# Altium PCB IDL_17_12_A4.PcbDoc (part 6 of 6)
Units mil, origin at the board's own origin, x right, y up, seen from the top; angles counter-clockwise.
Board outline 3172.06 x 10350 mil, 6 copper layers (Top Signal, Mid Signal, 3.3 Volt, GND, 5 Volt, Bot Signal), stack 122.8 mil thick; 332 components, 120 nets, 1937 pads, 197 vias.
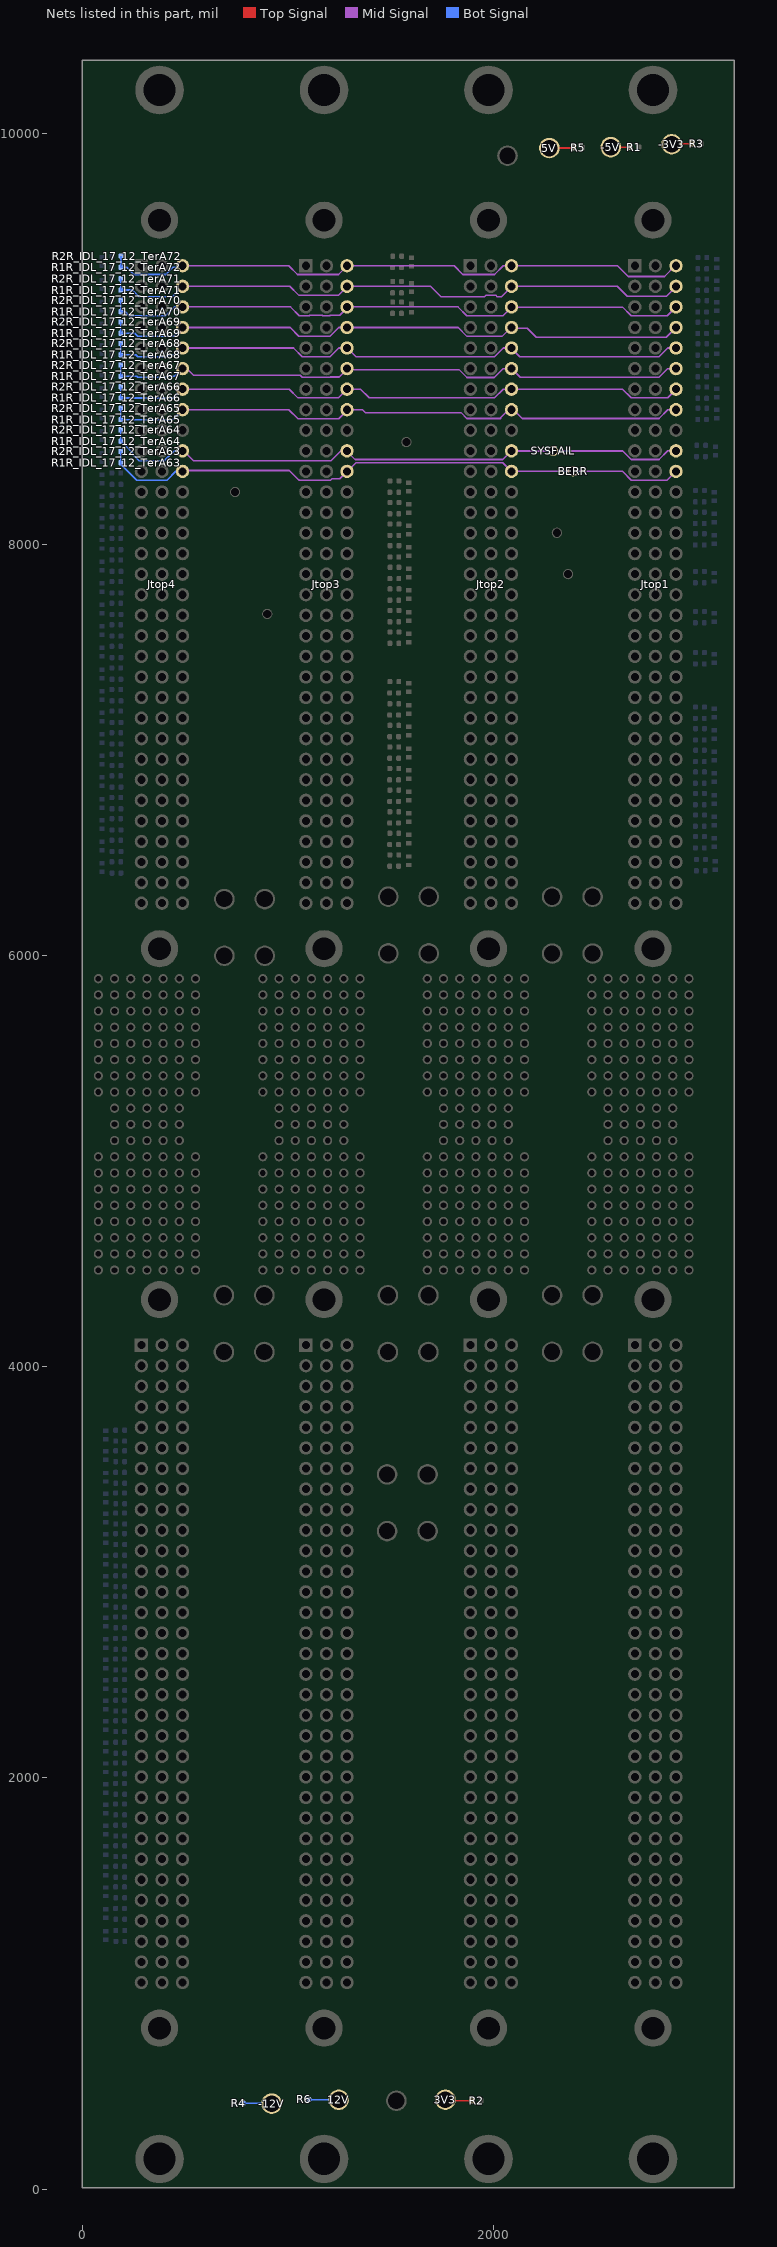
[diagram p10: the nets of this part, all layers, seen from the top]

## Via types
v1: diameter 25.59, hole 12, Top Signal to Bot Signal, 197 vias

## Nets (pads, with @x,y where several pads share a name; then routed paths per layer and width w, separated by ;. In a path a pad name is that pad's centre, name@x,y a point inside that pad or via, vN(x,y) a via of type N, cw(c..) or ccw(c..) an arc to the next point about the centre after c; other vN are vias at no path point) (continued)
JT63: BERR.1 Jtop1.C11 Jtop2.C11 Jtop3.C11 Jtop4.C11 R1R_IDL_17_12_TerA63.1 R2R_IDL_17_12_TerA63.2 | length 2955.1
  Mid Signal w8: Jtop4.C11@488.16,8354.97 488.16,8359.11 1007.69,8359.11 1052.43,8314.37 1052.76,8314.7 1056.02,8311.45 1207.56,8311.45 1215.18,8319.06 1253.26,8319.06 Jtop3.C11@1288.53,8354.33 ; Jtop3.C11@1288.61,8354.56 1331.5,8397.45 2045.68,8397.45 Jtop2.C11@2088.16,8354.97 2387.48,8354.97 2628.08,8354.97 2670.57,8312.48 2844.25,8312.48 2887.44,8355.68 2887.93,8356.16 Jtop1.C11@2888.16,8354.97
  Bot Signal w8: R2R_IDL_17_12_TerA63.2@187.5,8451.99 187.5,8424.61 ; R1R_IDL_17_12_TerA63.1@188.37,8396.97 188.37,8423.73 187.5,8424.61 ; Jtop4.C11@488.16,8354.97 455.51,8354.97 412.28,8311.73 265.28,8311.73 187.5,8389.52 187.5,8396.97 187.5,8424.61
JT64: Jtop1.C10 Jtop2.C10 Jtop3.C10 Jtop4.C10 R1R_IDL_17_12_TerA64.1 R2R_IDL_17_12_TerA64.2 SYSFAIL.1 | length 2942.3
  Mid Signal w8: Jtop4.C10@488.16,8454.97 488.9,8458.48 490.29,8457.09 541.31,8406.07 1210,8406.07 1258.89,8454.97 Jtop3.C10@1284.9,8454.97 ; Jtop3.C10@1283.19,8456.67 Jtop3.C10@1284.9,8454.97 ; Jtop3.C10@1288.16,8454.97 Jtop3.C10@1284.9,8454.97 ; Jtop2.C10@2084.72,8453.96 Jtop2.C10@2087.16,8453.96 ; Jtop2.C10@2088.16,8454.97 Jtop2.C10@2087.16,8453.96 ; Jtop1.C10@2888.16,8454.97 2848.24,8454.97 2805.76,8412.49 2670.57,8412.49 2629.09,8453.96 2290.4,8453.96 2088.16,8453.96 Jtop2.C10@2087.16,8453.96 ; Jtop3.C10@1284.9,8454.97 1286.53,8453.34 1327.38,8412.49 2045.68,8412.49 Jtop2.C10@2087.16,8453.96
  Bot Signal w8: R2R_IDL_17_12_TerA64.2@187.5,8556.99 187.5,8505.93 R1R_IDL_17_12_TerA64.1@189.68,8503.74 ; R1R_IDL_17_12_TerA64.1@188.37,8501.97 245.68,8444.66 245.68,8437.37 276.7,8406.36 399.63,8406.36 447.31,8454.04 488.16,8454.04 Jtop4.C10@488.95,8454.04
JT65: Jtop1.C8 Jtop2.C8 Jtop3.C8 Jtop4.C8 R1R_IDL_17_12_TerA65.1 R2R_IDL_17_12_TerA65.2 | length 2941.2
  Mid Signal w8: Jtop4.C8@488.16,8654.97 1005.35,8654.97 1049.34,8610.98 1247.85,8610.98 1287.24,8650.36 Jtop3.C8@1288.16,8654.97 ; Jtop3.C8@1293.11,8654.33 Jtop3.C8@1288.16,8654.97 ; 2031.79,8612.84 2073.92,8654.97 Jtop2.C8@2088.16,8654.97 2088.16,8675.73 2102.28,8675.73 2102.28,8654.97 2102.28,8654.38 2098.34,8654.38 2140.24,8612.48 2805.76,8612.48 2848.24,8654.97 Jtop1.C8@2888.16,8654.97 ; 2034.68,8612.49 1870.57,8612.49 1842.09,8640.97 1377.46,8640.97 1363.46,8654.97 Jtop3.C8@1288.16,8654.97
  Bot Signal w8: R2R_IDL_17_12_TerA65.2@187.5,8661.99 187.5,8634.61 188.37,8633.73 R1R_IDL_17_12_TerA65.1@188.37,8606.97 440.16,8606.97 Jtop4.C8@488.16,8654.97
JT66: Jtop1.C7 Jtop2.C7 Jtop3.C7 Jtop4.C7 R1R_IDL_17_12_TerA66.1 R2R_IDL_17_12_TerA66.2 | length 2886.7
  Mid Signal w8: Jtop4.C7@488.16,8754.96 1006.98,8754.96 1049.66,8712.28 1246.09,8712.28 1285.91,8752.1 Jtop3.C7@1288.16,8754.96 1289.57,8754.96 1289.57,8751.92 1290.38,8752.74 1292.61,8754.96 1353.33,8754.96 1395.8,8712.49 2005.76,8712.49 2048.24,8754.96 Jtop2.C7@2088.16,8754.96 2628.09,8754.96 2670.57,8712.49 2848.12,8712.49 2889.38,8753.75 2889.6,8753.97 Jtop1.C7@2888.16,8754.97
  Bot Signal w8: R2R_IDL_17_12_TerA66.2@187.5,8766.99 187.5,8715.42 189.66,8713.25 R1R_IDL_17_12_TerA66.1@190.95,8711.97 ; R1R_IDL_17_12_TerA66.1@188.37,8711.97 R1R_IDL_17_12_TerA66.1@190.95,8711.97 ; Jtop4.C7@488.16,8754.96 483.37,8753.81 441.53,8711.97 R1R_IDL_17_12_TerA66.1@190.95,8711.97
JT67: Jtop1.C6 Jtop2.C6 Jtop3.C6 Jtop4.C6 R1R_IDL_17_12_TerA67.1 R2R_IDL_17_12_TerA67.2 | length 2886
  Mid Signal w8: Jtop4.C6@488.16,8854.97 508.81,8854.97 541.83,8821.95 1061.1,8821.95 1070.57,8812.49 1105.76,8812.49 1106.38,8813.1 1169.01,8813.1 1169.63,8812.49 1205.76,8812.49 1207.31,8814.04 1250.52,8814.04 1289.8,8853.32 1290.34,8853.85 Jtop3.C6@1288.16,8854.97 ; Jtop3.C6@1289.09,8850.06 1832.99,8850.06 1871.6,8811.45 2004.72,8811.45 2048.24,8854.97 Jtop2.C6@2088.16,8854.97 ; Jtop2.C6@2089.74,8853.81 2131.06,8812.49 2805.76,8812.49 2848.24,8854.97 Jtop1.C6@2888.16,8854.97
  Bot Signal w8: R2R_IDL_17_12_TerA67.2@187.5,8871.99 187.5,8821.43 R1R_IDL_17_12_TerA67.1@190.17,8818.76 ; R1R_IDL_17_12_TerA67.1@188.37,8816.97 266.09,8816.97 270.57,8812.49 405.76,8812.49 410.24,8816.97 449.65,8816.97 487.9,8855.22 Jtop4.C6@492.5,8859.82
JT68: Jtop1.C5 Jtop2.C5 Jtop3.C5 Jtop4.C5 R1R_IDL_17_12_TerA68.1 R2R_IDL_17_12_TerA68.2 | length 2900.6
  Mid Signal w8: Jtop4.C5@488.16,8954.97 1028.09,8954.97 1070.57,8912.49 1205.76,8912.49 1248.24,8954.97 1286.84,8954.97 Jtop3.C5@1287.33,8954.48 ; Jtop3.C5@1288.16,8954.96 1286.35,8958.42 1288.98,8955.79 1332.29,8912.49 2005.76,8912.49 2048.24,8954.97 Jtop2.C5@2085.3,8954.97 ; Jtop2.C5@2083.81,8956.45 Jtop2.C5@2085.3,8954.97 ; Jtop2.C5@2088.16,8954.97 Jtop2.C5@2085.3,8954.97 ; Jtop1.C5@2888.16,8954.97 2848.24,8954.97 2805.76,8912.49 2127.78,8912.49 2086.73,8953.54 Jtop2.C5@2085.3,8954.97
  Bot Signal w8: R1R_IDL_17_12_TerA68.1@185.63,8917.14 187.5,8919.01 187.5,8921.97 R2R_IDL_17_12_TerA68.2@187.5,8976.99 ; R1R_IDL_17_12_TerA68.1@188.37,8921.97 261.08,8921.97 270.57,8912.48 405.76,8912.48 415.24,8921.97 459.29,8921.97 490.22,8952.9 Jtop4.C5@490.47,8953.15
JT69: Jtop1.C4 Jtop2.C4 Jtop3.C4 Jtop4.C4 R1R_IDL_17_12_TerA69.1 R2R_IDL_17_12_TerA69.2 | length 2890
  Mid Signal w8: Jtop4.C4@488.16,9054.97 1011.36,9054.97 1053.84,9012.49 1205.76,9012.49 1248.24,9054.97 Jtop3.C4@1288.16,9054.97 1288.6,9054.97 1290.05,9053.51 1291.71,9054.62 1828.43,9054.62 1871.6,9011.45 2042,9011.45 2086.84,9056.29 Jtop2.C4@2088.6,9058.04 ; Jtop2.C4@2090.82,9050.99 2164.85,9050.99 2208.4,9007.44 2840.64,9007.44 Jtop1.C4@2888.16,9054.97
  Bot Signal w8: R1R_IDL_17_12_TerA69.1@186.64,9023.66 187.5,9024.51 187.5,9026.97 R2R_IDL_17_12_TerA69.2@187.5,9081.99 ; R1R_IDL_17_12_TerA69.1@188.37,9026.97 256.09,9026.97 270.57,9012.49 445.32,9012.49 Jtop4.C4@487.43,9054.6
JT70: Jtop1.C3 Jtop2.C3 Jtop3.C3 Jtop4.C3 R1R_IDL_17_12_TerA70.1 R2R_IDL_17_12_TerA70.2 | length 2898.1
  Mid Signal w8: Jtop4.C3@488.16,9154.96 1012.93,9154.96 1055.41,9112.48 1105.76,9112.48 1107.19,9113.92 1169.13,9113.92 1170.57,9112.48 1205.76,9112.48 1207.19,9113.92 1253.26,9113.92 1290.28,9150.94 Jtop3.C3@1288.16,9154.97 1828.08,9154.97 1870.57,9112.48 2047.21,9112.48 2088.8,9154.08 2628.02,9154.08 2668.45,9113.65 ; 2668.93,9114.12 2670.57,9112.48 2846.44,9112.48 2888.54,9154.58 Jtop1.C3@2890.26,9156.3
  Bot Signal w8: R2R_IDL_17_12_TerA70.2@187.5,9186.99 187.5,9134.55 189.22,9132.82 R1R_IDL_17_12_TerA70.1@190.08,9131.97 ; R1R_IDL_17_12_TerA70.1@188.37,9131.97 191.05,9130.99 R1R_IDL_17_12_TerA70.1@190.08,9131.97 ; Jtop4.C3@488.16,9154.96 448.24,9154.96 405.01,9111.73 229.28,9111.73 209.05,9131.97 R1R_IDL_17_12_TerA70.1@190.08,9131.97
JT71: Jtop1.C2 Jtop2.C2 Jtop3.C2 Jtop4.C2 R1R_IDL_17_12_TerA71.1 R2R_IDL_17_12_TerA71.2 | length 2926
  Mid Signal w8: Jtop4.C2@488.16,9254.97 1010.14,9254.97 1052.62,9212.48 1247.93,9212.48 1289.28,9253.84 Jtop3.C2@1290.41,9254.97 ; Jtop3.C2@1288.16,9254.97 Jtop3.C2@1290.41,9254.97 ; Jtop1.C2@2888.16,9254.97 2892.49,9256.69 2889.47,9253.66 2842.3,9206.49 2651.57,9206.49 2603.1,9254.97 Jtop2.C2@2088.16,9254.97 2088.16,9250.01 2085.71,9250.01 2040.84,9205.14 2017.86,9205.14 2011.56,9211.45 1964.77,9211.45 1958.46,9205.14 1743.75,9205.14 1693.92,9254.97 Jtop3.C2@1290.41,9254.97
  Bot Signal w8: R2R_IDL_17_12_TerA71.2@187.5,9291.99 187.5,9264.61 188.37,9263.73 R1R_IDL_17_12_TerA71.1@188.37,9236.97 244.05,9236.97 276.28,9204.73 437.93,9204.73 Jtop4.C2@488.16,9254.97
JT72: Jtop1.C1 Jtop2.C1 Jtop3.C1 Jtop4.C1 R1R_IDL_17_12_TerA72.1 R2R_IDL_17_12_TerA72.2 | length 2901.5
  Mid Signal w8: Jtop4.C1@488.16,9354.97 1004.72,9354.97 1047.2,9312.49 1246.89,9312.49 Jtop3.C1@1287.43,9353.03 ; Jtop3.C1@1288.16,9354.97 1809.06,9354.97 1851.54,9312.49 2005.76,9312.49 2048.24,9354.97 Jtop2.C1@2088.16,9354.97 2603.6,9354.97 2655.51,9303.06 2832.17,9303.06 2886.12,9357.01 Jtop1.C1@2886.66,9357.56
  Bot Signal w8: R1R_IDL_17_12_TerA72.1@188.36,9347.52 216.51,9347.52 251.54,9312.49 405.76,9312.49 440.79,9347.52 484.13,9347.52 489.87,9353.26 490.47,9353.86 Jtop4.C1@488.16,9354.97 ; R2R_IDL_17_12_TerA72.2@188.62,9402.03 188.62,9348.33 R1R_IDL_17_12_TerA72.1@188.67,9348.28
TP3V3_2: 3V3.1@1766.37,434.93 R2.1 | length 129.2
  Top Signal w8: 3V3.1@1769.47,435.28 1774.83,429.92 R2.1@1896.47,429.92
TP5V_2: 5V.1@2272.26,9927.69 R5.1 | length 126.3
  Top Signal w8: 5V.1@2265.37,9928.08 2272.26,9928.08 2390.15,9928.08 R5.1@2391.2,9929.14
TP12V_2: 12V.1@1247.83,434.61 R6.1 | length 144.6
  Bot Signal w8: R6.1@1101.56,435.56 1102.44,435.56 1244.33,435.56 12V.1@1245.61,436.84
TP-3V3_2: -3V3.1@2867.29,9946.36 R3.1 | length 77.9
  Top Signal w8: -3V3.1@2890.7,9951.9 2893.87,9948.74 R3.1@2967.27,9948.74
TP-5V_2: -5V.1@2571.02,9932.41 R1.1 | length 83
  Top Signal w8: -5V.1@2582.33,9930.01 2584.05,9931.73 R1.1@2664.58,9931.73
TP-12V_2: -12V.1@921.62,416.17 R4.1 | length 136.6
  Bot Signal w8: R4.1@782.89,417.54 912.71,417.54 916.48,421.31 -12V.1@917.5,422.32
pads on no net: Jbot1.33 Jbot1.34 Jbot1.A1 Jbot1.A2 Jbot1.A3 Jbot1.A4 Jbot1.A5 Jbot1.A6 Jbot1.A7 Jbot1.A8 Jbot1.A9 Jbot1.A10 Jbot1.A11 Jbot1.A12 Jbot1.A13 Jbot1.A14 Jbot1.A15 Jbot1.A16 Jbot1.A17 Jbot1.A18 Jbot1.A19 Jbot1.A20 Jbot1.A21 Jbot1.A22 Jbot1.A23 Jbot1.A24 Jbot1.A25 Jbot1.A26 Jbot1.A27 Jbot1.A28 Jbot1.A29 Jbot1.A30 Jbot1.A31 Jbot1.A32 Jbot1.C1 Jbot1.C2 Jbot1.C3 Jbot1.C4 Jbot1.C5 Jbot1.C6 Jbot1.C7 Jbot1.C8 Jbot1.C9 Jbot1.C10 Jbot1.C11 Jbot1.C12 Jbot1.C13 Jbot1.C14 Jbot1.C15 Jbot1.C16 Jbot1.C17 Jbot1.C18 Jbot1.C19 Jbot1.C20 Jbot1.C21 Jbot1.C22 Jbot1.C23 Jbot1.C24 Jbot1.C25 Jbot1.C26 Jbot1.C27 Jbot1.C28 Jbot1.C29 Jbot1.C30 Jbot1.C31 Jbot1.C32 Jbot2.33 Jbot2.34 Jbot2.A1 Jbot2.A2 Jbot2.A3 Jbot2.A4 Jbot2.A5 Jbot2.A6 Jbot2.A7 Jbot2.A8 Jbot2.A9 Jbot2.A10 Jbot2.A11 Jbot2.A12 Jbot2.A13 Jbot2.A14 Jbot2.A15 Jbot2.A16 Jbot2.A17 Jbot2.A18 Jbot2.A19 Jbot2.A20 Jbot2.A21 Jbot2.A22 Jbot2.A23 Jbot2.A24 Jbot2.A25 Jbot2.A26 Jbot2.A27 Jbot2.A28 Jbot2.A29 Jbot2.A30 Jbot2.A31 Jbot2.A32 Jbot2.C1 Jbot2.C2 Jbot2.C3 Jbot2.C4 Jbot2.C5 Jbot2.C6 Jbot2.C7 Jbot2.C8 Jbot2.C9 Jbot2.C10 Jbot2.C11 Jbot2.C12 Jbot2.C13 Jbot2.C14 Jbot2.C15 Jbot2.C16 Jbot2.C17 Jbot2.C18 Jbot2.C19 Jbot2.C20 Jbot2.C21 Jbot2.C22 Jbot2.C23 Jbot2.C24 Jbot2.C25 Jbot2.C26 Jbot2.C27 Jbot2.C28 Jbot2.C29 Jbot2.C30 Jbot2.C31 Jbot2.C32 Jbot3.33 Jbot3.34 Jbot3.A1 Jbot3.A2 Jbot3.A3 Jbot3.A4 Jbot3.A5 Jbot3.A6 Jbot3.A7 Jbot3.A8 Jbot3.A9 Jbot3.A10 Jbot3.A11 Jbot3.A12 Jbot3.A13 Jbot3.A14 Jbot3.A15 Jbot3.A16 Jbot3.A17 Jbot3.A18 Jbot3.A19 Jbot3.A20 Jbot3.A21 Jbot3.A22 Jbot3.A23 Jbot3.A24 Jbot3.A25 Jbot3.A26 Jbot3.A27 Jbot3.A28 Jbot3.A29 Jbot3.A30 Jbot3.A31 Jbot3.A32 Jbot3.C1 Jbot3.C2 Jbot3.C3 Jbot3.C4 Jbot3.C5 Jbot3.C6 Jbot3.C7 Jbot3.C8 Jbot3.C9 Jbot3.C10 Jbot3.C11 Jbot3.C12 Jbot3.C13 Jbot3.C14 Jbot3.C15 Jbot3.C16 Jbot3.C17 Jbot3.C18 Jbot3.C19 Jbot3.C20 Jbot3.C21 Jbot3.C22 Jbot3.C23 Jbot3.C24 Jbot3.C25 Jbot3.C26 Jbot3.C27 Jbot3.C28 Jbot3.C29 Jbot3.C30 Jbot3.C31 Jbot3.C32 Jbot4.33 Jbot4.34 Jbot4.A1 Jbot4.A2 Jbot4.A3 Jbot4.A4 Jbot4.A5 Jbot4.A6 Jbot4.A7 Jbot4.A8 Jbot4.A9 Jbot4.A10 Jbot4.A11 Jbot4.A12 Jbot4.A13 Jbot4.A14 Jbot4.A15 Jbot4.A16 Jbot4.A17 Jbot4.A18 Jbot4.A19 Jbot4.A20 Jbot4.A21 Jbot4.A22 Jbot4.A23 Jbot4.A24 Jbot4.A25 Jbot4.A26 Jbot4.A27 Jbot4.A28 Jbot4.A29 Jbot4.A30 Jbot4.A31 Jbot4.A32 Jbot4.C1 Jbot4.C2 Jbot4.C3 Jbot4.C4 Jbot4.C5 Jbot4.C6 Jbot4.C7 Jbot4.C8 Jbot4.C9 Jbot4.C10 Jbot4.C11 Jbot4.C12 Jbot4.C13 Jbot4.C14 Jbot4.C15 Jbot4.C16 Jbot4.C17 Jbot4.C18 Jbot4.C19 Jbot4.C20 Jbot4.C21 Jbot4.C22 Jbot4.C23 Jbot4.C24 Jbot4.C25 Jbot4.C26 Jbot4.C27 Jbot4.C28 Jbot4.C29 Jbot4.C30 Jbot4.C31 Jbot4.C32 JMid1.32 JMid1.33 JMid1.34 JMid1.35 JMid1.51 JMid1.52 JMid1.53 JMid1.54 JMid1.89 JMid1.90 JMid1.91 JMid1.92 JMid1.102 JMid1.103 JMid1.104 JMid1.106 JMid1.108 JMid1.109 JMid1.110 JMid1.111 JMid2.32 JMid2.33 JMid2.34 JMid2.35 JMid2.51 JMid2.52 JMid2.53 JMid2.54 JMid2.89 JMid2.90 JMid2.91 JMid2.92 JMid2.102 JMid2.103 JMid2.104 JMid2.106 JMid2.108 JMid2.109 JMid2.110 JMid2.111 JMid3.32 JMid3.33 JMid3.34 JMid3.35 JMid3.51 JMid3.52 JMid3.53 JMid3.54 JMid3.89 JMid3.90 JMid3.91 JMid3.92 JMid3.102 JMid3.103 JMid3.104 JMid3.106 JMid3.108 JMid3.109 JMid3.110 JMid3.111 JMid4.32 JMid4.33 JMid4.34 JMid4.35 JMid4.51 JMid4.52 JMid4.53 JMid4.54 JMid4.89 JMid4.90 JMid4.91 JMid4.92 JMid4.102 JMid4.103 JMid4.104 JMid4.106 JMid4.108 JMid4.109 JMid4.110 JMid4.111 Jtop1.33 Jtop1.34 Jtop2.33 Jtop2.34 Jtop3.33 Jtop3.34 Jtop4.33 Jtop4.34

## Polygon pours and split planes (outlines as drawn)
GND on Mid Signal "Mid Signal-No Net" (solid, remove dead copper, pour order 8): 288.97,2902.97 292.43,2899.5 2892.14,2899.5 2892.14,881.35 2781.37,770.58 2774.45,777.5 295.89,777.5 295.89,2909.89
12V on Mid Signal "12V" (solid, remove dead copper, pour order 4): 102.79,6460.34 110.33,6467.88 3031.85,6467.88 3031.85,5887.72 3028.09,5883.95 102.79,5883.95
-5V on Mid Signal "-5V" (solid, remove dead copper, pour order 0): 80.39,4937.59 82.87,4940.06 2954.79,4940.06 2949.84,3073.97 76.86,3073.97 82.87,3303.91 77.92,3563.42 77.92,3633.46
-3V3 on Top Signal "-3V3" (solid, remove dead copper, pour order 2): 72.6,5264.94 2949.49,5264.94 2949.49,3892.71 66.5,3892.71 56.18,3892.71
-12V on Top Signal "-12V" (solid, remove dead copper, pour order 6): 226.59,6445.99 2946.13,6445.99 2946.13,5895.87 226.59,5895.87
-12V on Top Solder "-12V" (solid, remove dead copper): 104.53,6466.91 3032.29,6466.91 3034.17,6465.03 3024.77,6455.63 3024.77,5891.52 102.65,5891.52
3V3 on 3.3 Volt (split plane): 3151.24,25.83 20.37,25.83 20.37,10335.64 3151.24,10335.64
GND on GND (split plane): 3151.24,25.83 19.38,25.83 19.38,10335.64 3151.24,10335.64
5V on 5 Volt (split plane): 3151.24,25.83 20.37,25.83 20.37,10335.64 3151.24,10335.64

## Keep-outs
Keep-Out Layer:
  lines w20: -0.72,5.73 -0.72,10355.73

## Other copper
3.3 Volt (plane layer: these items are gaps in the copper):
  lines w20: 10.28,16.73 10.28,10344.73
5 Volt (plane layer: these items are gaps in the copper):
  lines w20: 10.28,16.73 10.28,10344.73

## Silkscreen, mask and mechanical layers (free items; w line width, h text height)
Top Overlay:
  lines w10: 58.79,5133.09 101.87,5133.09 101.87,5219.98 58.79,5219.98 58.79,5133.09 ; 856.31,5137.1 856.31,5223.99 899.39,5223.99 899.39,5137.1 856.31,5137.1 ; 1655.2,5137.36 1655.2,5224.24 1698.28,5224.24 1698.28,5137.36 1655.2,5137.36 ; 2442.3,5138.09 2442.3,5224.97 2485.38,5224.97 2485.38,5138.09 2442.3,5138.09
  lines w15.66: 524.81,5107.15 524.81,5243.24 592.29,5243.24 592.29,5107.15 524.81,5107.15 ; 1327.71,5110.36 1395.19,5110.36 1395.19,5246.44 1327.71,5246.44 1327.71,5110.36 ; 2120.23,5112.58 2187.71,5112.58 2187.71,5248.66 2120.23,5248.66 2120.23,5112.58 ; 2922.08,5112.43 2989.56,5112.43 2989.56,5248.51 2922.08,5248.51 2922.08,5112.43
  text "1" at 2477.89,9369.12 h60 r270
Bottom Overlay:
  drawing of 175 lines, arcs and shapes, not listed
  text "Jtop1" at 3095.97,9777.19 h60 r90
  text "IDL_17_012 / VME32/COPPER Backplane Rev.A / Designer: Jose Duron" at 1393.36,9710.53 h60
  text "A" at 1867.39,9406.06 h60 r270
  text "A" at 268.09,9402.68 h60 r270
  text "A" at 1070.53,9402.97 h60 r270
  text "A" at 2669.1,9400.38 h60 r270
  text "1" at 2476.52,9369.05 h60 r270
  text "1" at 573.67,9345.91 h60 r270
  text "1" at 1687.9,9339.53 h60 r270
  text "1" at 884.85,9333.34 h60 r270
  text "Jtop2" at 2301.94,8938.18 h60 r90
  text "Jtop3" at 1496.66,8906.68 h60 r90
  text "Jtop4" at 698.13,8884.19 h60 r90
  text "A" at 1862.51,4169.68 h60 r270
  text "A" at 1069.57,4162.63 h60 r270
  text "A" at 2673.02,4159.87 h60 r270
  text "A" at 266.75,4153.77 h60 r270
  text "1" at 3031.33,4100.24 h60 r270
  text "1" at 93.15,4098.79 h60 r270
  text "Jbot1" at 3033.07,3692.03 h60 r270
  text "Jbot2" at 2240.98,3658.98 h60 r270
  text "Jbot3" at 1441.16,3656.08 h60 r270
  text "Jbot4" at 643.73,3642.43 h60 r270
  text "32" at 875.14,1058.14 h60 r270
  text "32" at 89.93,1054.84 h60 r270
  text "32" at 1673.55,1051.54 h60 r270
  text "32" at 2490.02,1034.47 h60 r270
  text "235R" at 495.8,584.18 h60
  text "1uF" at 126.22,548.13 h60 r90
  text "IDL" at 2699,454.09 h50
  text "Instrumentation" at 2699,404.09 h25
  text "Development" at 2699.26,364.1 h25
  text "Lab" at 2699,324.09 h25
  text "165R" at 489.79,295.73 h60
Board Outline:
  lines w20: -0.72,5.73 3174.67,5.73 3176.89,7.95 3176.89,10353.29 1.73,10353.29 -0.72,10355.73 -0.72,5.73
Sheet Top:
  lines w3.9: -1790.05,1459.24 -1690.05,1459.24 ; -1790.05,3372.58 -1690.05,3372.58 ; -1790.05,5285.91 -1690.05,5285.91 ; -1790.05,7199.24 -1690.05,7199.24 ; -1790.05,9112.58 -1690.05,9112.58 ; 184.95,-454.09 184.95,-354.09 ; 184.95,10925.91 184.95,11025.91 ; 2159.95,-454.09 2159.95,-354.09 ; 2159.95,10925.91 2159.95,11025.91 ; 4134.95,-454.09 4134.95,-354.09 ; 4134.95,10925.91 4134.95,11025.91 ; 6109.95,-454.09 6109.95,-354.09 ; 6109.95,10925.91 6109.95,11025.91 ; 8084.95,-454.09 8084.95,-354.09 ; 8084.95,10925.91 8084.95,11025.91 ; 10059.95,-454.09 10059.95,-354.09 ; 10059.95,10925.91 10059.95,11025.91 ; 12034.95,-454.09 12034.95,-354.09 ; 12034.95,10925.91 12034.95,11025.91 ; 13909.95,1459.24 14009.95,1459.24 ; 13909.95,3372.58 14009.95,3372.58 ; 13909.95,5285.91 14009.95,5285.91 ; 13909.95,7199.24 14009.95,7199.24 ; 13909.95,9112.58 14009.95,9112.58 ; -1790.05,-453.99 14009.86,-453.99 14009.86,11025.91 -1790.05,11025.91 -1790.05,-453.99 ; -1689.79,-354.29 13909.6,-354.29 13909.6,10926.2 -1689.79,10926.2 -1689.79,-354.29
  lines w3.94: 7219.95,-354.29 7219.95,355.91 13909.6,355.91 ; 7219.95,-3.33 13909.95,-3.33 ; 7219.95,115.91 12039.95,115.91 ; 7219.95,235.91 12039.95,235.91 ; 8724.95,-3.33 8724.95,355.91 ; 9724.95,-3.33 9724.95,355.91 ; 11314.95,-3.33 11314.95,355.91 ; 12039.95,-354.29 12039.95,355.91 ; 12039.95,175.91 13909.6,175.91
  text "1" at -822.73,10946.39 h35
  text "2" at 1152.27,10946.39 h35
  text "3" at 3127.27,10946.39 h35
  text "4" at 5102.27,10946.39 h35
  text "5" at 7077.27,10946.39 h35
  text "6" at 9052.27,10946.39 h35
  text "7" at 11027.27,10946.39 h35
  text "8" at 13002.27,10946.39 h35
  text "A" at -1765.28,9989.24 h35
  text "A" at 13934.72,9989.24 h35
  text "B" at -1765.28,8075.91 h35
  text "B" at 13934.72,8075.91 h35
  text "C" at -1770.32,6162.58 h35
  text "C" at 13929.68,6162.58 h35
  text "D" at -1770.32,4249.24 h35
  text "D" at 13929.68,4249.24 h35
  text "E" at -1765.28,2335.91 h35
  text "E" at 13934.72,2335.91 h35
  text "F" at -1765.28,422.58 h35
  text "F" at 13934.72,422.58 h35
  text "Designer:" at 7244.95,265.91 h100
  text ".Designer" at 7809.95,260.91 h100
  text "Revision:" at 8749.95,260.91 h100
  text ".RevNum" at 9309.95,260.91 h100
  text "File:" at 9749.95,260.91 h100
  text ".Pcb_File_Name_No_Path" at 9949.95,260.91 h100
  text "Sheet  1 of  1" at 11344.95,260.91 h100
  text "Code:" at 12064.95,215.91 h100
  text "Drawn By:" at 7244.95,145.91 h100
  text ".Drawn_By" at 7809.95,145.91 h100
  text "Modif. Date:" at 8749.95,140.91 h100
  text "Date" at 9254.95,140.91 h100
  text "Variant:" at 9749.95,140.91 h100
  text ".VariantName" at 10114.95,140.91 h100
  text "ID:" at 12069.95,35.91 h100
  text "Approved By:" at 7244.95,25.91 h100
  text ".Approved_By" at 7809.95,25.91 h100
  text ".Print_Date" at 9197.35,21.5 h100
  text "Print Date:" at 8749.95,20.91 h100
  text "Signature:" at 9749.95,20.91 h100
  text "Size:  A3 H" at 11344.95,20.91 h100
  text "Title:" at 7244.95,-104.09 h100
  text "University of Hawaii at Manoa" at 12071.36,-112.36 h100
  text "High Energy Physics Group" at 12071.36,-210.78 h100
  text ".Printout_Name" at 7469.95,-244.09 h160
  text "Instrumentation Development Laboratory" at 12071.36,-313.15 h100
  text "1" at -822.73,-433.61 h35
  text "2" at 1152.27,-433.61 h35
  text "3" at 3127.27,-433.61 h35
  text "4" at 5102.27,-433.61 h35
  text "5" at 7077.27,-433.61 h35
  text "6" at 9052.27,-433.61 h35
  text "7" at 11027.27,-433.61 h35
  text "8" at 13002.27,-433.61 h35
Drill Drawing:
  drawing of 469 lines, arcs and shapes, not listed
  text "Notes:" at 7964.04,9029 h130
  text "1. Board shall be fabricated - performace class II as per IPC-6011 and IPC6012" at 7964.04,8904 h100
  text "2. Silkscreen printed on both sides" at 7967.15,8771.96 h100
  text "3. Material: high temperature FR4 class epoxy glass rated UL94V-0. UL symbol and rating shall be marked farside" at 7967.15,8646.96 h100
  text "35um copper for external and internal layers" at 8067.17,8546.96 h100
  text "Must be RoHS compliant and survive a lead-free assembly max reflow of 260 deg C (5 passes)" at 8067.15,8446.96 h100
  text "Td rating: >340 deg C" at 8117.15,8321.96 h100
  text "Tg = 150 deg C (min)" at 8121.18,8211.7 h100
  text "4. Solder mask: SMOBC per IPC-SM-840C, class T must be Rohs compliant, 0.001\" max measured over bare copper plating," at 7967.15,8101.88 h100
  text "must clear all lands as indicated on gerber solder mask layers, color= GREEN" at 8067.15,8001.88 h100
  text "5. Finish: electro-less nickel immersion gold (ENIG), 2.95-4.92uin Au over 118-236uin Ni - over bare copper only" at 7966.94,7848.06 h100
  text "6. Solderability test: Category 2 of J-STD-003" at 7967.15,7701.88 h100
  text "7. Finished boards shall not have nicks, scratches, voids, exposed copper, poor plating or misdrilled holes" at 7967.15,7551.88 h100
  text "8. All holes sizes are after plating" at 7967.15,7401.88 h100
  text "9. PCB manufacturer may add copper thieving as needed to improve manufacturability," at 7961.57,7250.09 h100
  text "thieving to be 0.030\" round pads at 0.050\" spacing." at 8067.15,7151.88 h100
  text "Thieving will have a minimum of 0.100\" clearance from existing copper and should not be placed under surface mounted devices" at 8067.15,7051.88 h100
  text "10. PCB manufacturer may use tear drops to improve annular rings as long as DRC rules are followed" at 7922.15,6911.88 h100
  text "11. All via connections to power and ground planes are solid" at 7922.15,6771.88 h100
  text "12. All unconnected pads on inner signal layers are removed" at 7922.15,6631.88 h100
  text "13. All finished boards are to be 100% electrically tested" at 7922.17,6491.88 h100
  text "14. Unless otherwise indicated, all linear toleracnes shall be XX.X +/-0.2mm and XX.XX +/- 0.1mm" at 7922.15,6351.88 h100
  text "15. Gerber file GM9 shows board outline (milling line)" at 7922.14,6211.86 h100
  text "16. Table 1 shows Layer stack details" at 7922.13,6071.85 h100
  text "Symbol" at 7825.67,3845.07 h72
  text "Count" at 8331.55,3845.07 h72
  text "Hole Size" at 8981.37,3845.07 h72
  text "Plated" at 10131.04,3845.07 h72
  text "Hole Type" at 10636.91,3845.07 h72
  text "Hole Length" at 11370.71,3845.07 h72
  text "8" at 8331.55,3695.07 h60
  text "80.00mil (2.032mm)" at 8981.37,3695.07 h60
  text "PTH" at 10131.04,3695.07 h60
  text "Round" at 10636.91,3695.07 h60
  text "-" at 11370.71,3695.07 h60
  text "8" at 8331.55,3545.07 h60
  text "157.00mil (3.988mm)" at 8981.37,3545.07 h60
  text "PTH" at 10131.04,3545.07 h60
  text "Round" at 10636.91,3545.07 h60
  text "-" at 11370.71,3545.07 h60
  text "16" at 8331.55,3395.07 h60
  text "110.24mil (2.800mm)" at 8981.37,3395.07 h60
  text "PTH" at 10131.04,3395.07 h60
  text "Round" at 10636.91,3395.07 h60
  text "-" at 11370.71,3395.07 h60
  text "28" at 8331.55,3245.07 h60
  text "78.74mil (2.000mm)" at 8981.37,3245.07 h60
  text "PTH" at 10131.04,3245.07 h60
  text "Round" at 10636.91,3245.07 h60
  text "-" at 11370.71,3245.07 h60
  text "197" at 8331.55,3095.07 h60
  text "12.00mil (0.305mm)" at 8981.37,3095.07 h60
  text "PTH" at 10131.04,3095.07 h60
  text "Round" at 10636.91,3095.07 h60
  text "-" at 11370.71,3095.07 h60
  text "508" at 8331.55,2945.07 h60
  text "27.56mil (0.700mm)" at 8981.37,2945.07 h60
  text "PTH" at 10131.04,2945.07 h60
  text "Round" at 10636.91,2945.07 h60
  text "-" at 11370.71,2945.07 h60
  text "775" at 8331.55,2795.07 h60
  text "39.37mil (1.000mm)" at 8981.37,2795.07 h60
  text "PTH" at 10131.04,2795.07 h60
  text "Round" at 10636.91,2795.07 h60
  text "-" at 11370.71,2795.07 h60
  text "1540 Total" at 8331.55,2645.07 h60
  text "Layer" at 7785.75,2376.28 h60
  text "Name" at 8195.66,2376.28 h60
  text "Material" at 9125.41,2376.28 h60
  text "Thickness" at 9985.18,2376.28 h60
  text "Constant" at 10635.01,2376.28 h60
  text "Board Layer Stack" at 11204.87,2376.28 h60
  text "1" at 7785.75,2256.28 h60
  text "Top Overlay" at 8195.66,2256.28 h60
  text "2" at 7785.75,2136.28 h60
  text "Top Solder" at 8195.66,2136.28 h60
  text "Solder Resist" at 9125.41,2136.28 h60
  text "0.40mil" at 9985.18,2136.28 h60
  text "3.5" at 10635.01,2136.28 h60
  text "3" at 7785.75,2016.28 h60
  text "Top Signal" at 8195.66,2016.28 h60
  text "Copper" at 9125.41,2016.28 h60
  text "1.35mil" at 9985.18,2016.28 h60
  text "4" at 7785.75,1896.28 h60
  text "Dielectric 1" at 8195.66,1896.28 h60
  text "FR-4" at 9125.41,1896.28 h60
  text "10.00mil" at 9985.18,1896.28 h60
  text "4.2" at 10635.01,1896.28 h60
  text "5" at 7785.75,1776.28 h60
  text "Mid Signal" at 8195.66,1776.28 h60
  text "Copper" at 9125.41,1776.28 h60
  text "1.35mil" at 9985.18,1776.28 h60
  text "6" at 7785.75,1656.28 h60
  text "Dielectric 6" at 8195.66,1656.28 h60
  text "FR-4" at 9125.41,1656.28 h60
  text "40.00mil" at 9985.18,1656.28 h60
  text "4.2" at 10635.01,1656.28 h60
  text "7" at 7785.75,1536.28 h60
  text "3.3 Volt" at 8195.66,1536.28 h60
  text "Copper" at 9125.41,1536.28 h60
  text "2.70mil" at 9985.18,1536.28 h60
  text "8" at 7785.75,1416.28 h60
  text "Dielectric 5" at 8195.66,1416.28 h60
  text "FR-4" at 9125.41,1416.28 h60
  text "12.00mil" at 9985.18,1416.28 h60
  text "4.2" at 10635.01,1416.28 h60
  text "9" at 7785.75,1296.28 h60
  text "GND" at 8195.66,1296.28 h60
  text "Copper" at 9125.41,1296.28 h60
  text "2.70mil" at 9985.18,1296.28 h60
  text "10" at 7785.75,1176.28 h60
  text "Dielectric2" at 8195.66,1176.28 h60
  text "FR-4" at 9125.41,1176.28 h60
  text "40.00mil" at 9985.18,1176.28 h60
  text "4.2" at 10635.01,1176.28 h60
  text "11" at 7785.75,1056.28 h60
  text "5 Volt" at 8195.66,1056.28 h60
  text "Copper" at 9125.41,1056.28 h60
  text "1.35mil" at 9985.18,1056.28 h60
  text "12" at 7785.75,936.28 h60
  text "Dielectric 7" at 8195.66,936.28 h60
  text "10.00mil" at 9985.18,936.28 h60
  text "4.2" at 10635.01,936.28 h60
  text "13" at 7785.75,816.28 h60
  text "Bot Signal" at 8195.66,816.28 h60
  text "Copper" at 9125.41,816.28 h60
  text "1.35mil" at 9985.18,816.28 h60
  text "14" at 7785.75,696.28 h60
  text "Bottom Solder" at 8195.66,696.28 h60
  text "Solder Resist" at 9125.41,696.28 h60
  text "0.40mil" at 9985.18,696.28 h60
  text "3.5" at 10635.01,696.28 h60
  text "15" at 7785.75,576.28 h60
  text "Bottom Overlay" at 8195.66,576.28 h60

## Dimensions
78.8,4470.19 to -0.72,5.73 on Mechanical 1
878.8,4470.19 to -0.72,5.73 on Mechanical 1
1678.8,4470.19 to -0.72,5.73 on Mechanical 1
2478.8,4470.19 to -0.72,5.73 on Mechanical 1
-0.72,5.73 to -0.72,10355.73 on Mechanical 1
-0.72,5.73 to 3171.34,5.73 on Mechanical 1
385.11,147.23 to -0.72,5.73 on Mechanical 1
376.35,783.31 to -0.72,5.73 on Mechanical 1
376.35,783.31 to -0.72,5.73 on Mechanical 1
376.35,6033.31 to -0.72,10355.73 on Mechanical 1
377.37,9576.62 to -0.72,5.73 on Mechanical 1
78.8,4470.19 to -0.72,5.73 on Mechanical 1
385.11,10210.23 to -0.72,5.73 on Mechanical 1
1177.37,9576.62 to -0.72,10355.73 on Mechanical 1
1977.37,9576.62 to -0.72,10355.73 on Mechanical 1
2777.37,9576.62 to -0.72,10355.73 on Mechanical 1
3176.89,10353.29 to -0.72,10355.73 on Mechanical 1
